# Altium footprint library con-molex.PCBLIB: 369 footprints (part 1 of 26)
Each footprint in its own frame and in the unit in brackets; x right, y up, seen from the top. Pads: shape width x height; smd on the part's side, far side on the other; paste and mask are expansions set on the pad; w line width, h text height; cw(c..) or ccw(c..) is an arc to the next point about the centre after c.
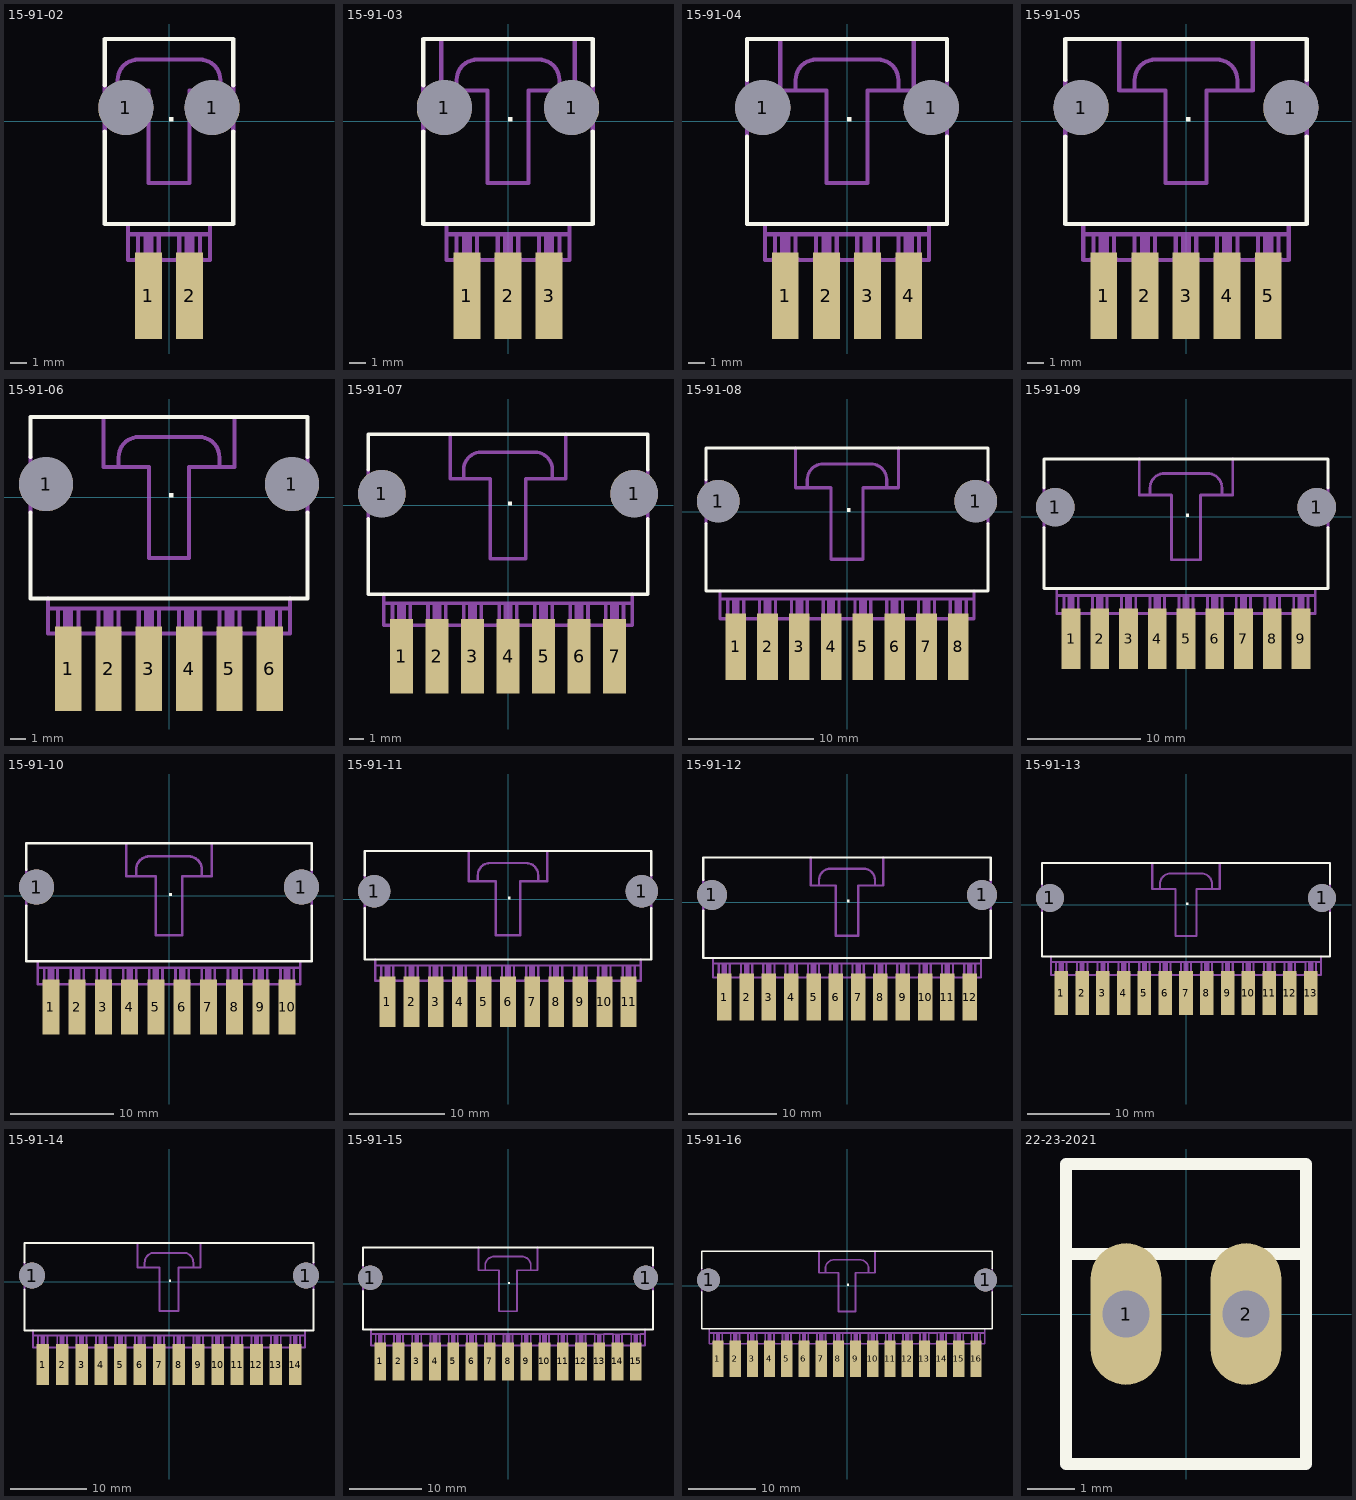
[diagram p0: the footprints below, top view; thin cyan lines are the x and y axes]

## 15-91-02 [mil]
pads (4):
  round 134 hole 134: 1(-105,33) 1(105,33)
  rect 65x210 smd: 1(-50,-425) 2(50,-425)
Top Overlay:
  region: 0,0 10,0 10,10 0,10
  lines w10: -156.25,-25 -156.25,-250 156.25,-250 156.25,-25 ; -156.25,87.5 -156.25,200 156.25,200 156.25,87.5
Mechanical 16:
  rectangle: 37.5,-425 62.5,-275
  rectangle: -62.5,-425 -37.5,-275
  lines w10: -156.25,-25 -156.25,75 ; -156.25,87.5 -156.25,75 ; -100,-275 -75,-275 ; -100,-250 -100,-337.5 -85,-337.5 ccw(c-85,-327.5) -75,-327.5 -75,-275 ; 100,-275 75,-275 ; 100,-250 100,-337.5 85,-337.5 cw(c85,-327.5) 75,-327.5 75,-275 ; 156.25,-25 156.25,75 ; 156.25,87.5 156.25,75 ; -156.25,75 -125,75 ; -125,75 -125,100 cw(c-75,100) -75,150 75,150 cw(c75,100) 125,100 125,75 ; -125,75 -50,75 -50,-150 50,-150 50,75 125,75 ; -75,-275 -25,-275 ; -25,-275 -25,-327.5 ccw(c-15,-327.5) -15,-337.5 15,-337.5 ccw(c15,-327.5) 25,-327.5 25,-275 ; -25,-275 25,-275 ; 25,-275 75,-275 ; 125,75 156.25,75

## 15-91-03 [mil]
pads (5):
  round 134 hole 134: 1(-155,33) 1(155,33)
  rect 65x210 smd: 1(-100,-425) 2(0,-425) 3(100,-425)
Top Overlay:
  region: 0,0 10,0 10,10 0,10
  lines w10: -206.25,-25 -206.25,-250 206.25,-250 206.25,-25 ; -206.25,87.5 -206.25,200 206.25,200 206.25,87.5
Mechanical 16:
  rectangle: 87.5,-425 112.5,-275
  rectangle: -12.5,-425 12.5,-275
  rectangle: -112.5,-425 -87.5,-275
  lines w10: -206.25,-25 -206.25,87.5 ; -162.5,200 -162.5,75 -125,75 ; -150,-275 -125,-275 ; -150,-250 -150,-337.5 -135,-337.5 ccw(c-135,-327.5) -125,-327.5 -125,-275 ; 150,-275 125,-275 ; 150,-250 150,-337.5 135,-337.5 cw(c135,-327.5) 125,-327.5 125,-275 ; 162.5,200 162.5,75 125,75 ; 206.25,-25 206.25,87.5 ; -125,-275 -75,-275 ; -125,75 -125,100 cw(c-75,100) -75,150 75,150 cw(c75,100) 125,100 125,75 ; -125,75 -50,75 -50,-150 50,-150 50,75 125,75 ; -75,-275 -75,-327.5 ccw(c-65,-327.5) -65,-337.5 -35,-337.5 ccw(c-35,-327.5) -25,-327.5 -25,-275 ; -75,-275 -25,-275 ; -25,-275 25,-275 ; 25,-275 25,-327.5 ccw(c35,-327.5) 35,-337.5 65,-337.5 ccw(c65,-327.5) 75,-327.5 75,-275 ; 25,-275 75,-275 ; 75,-275 125,-275

## 15-91-04 [mil]
pads (6):
  round 134 hole 134: 1(-205,33) 1(205,33)
  rect 65x210 smd: 1(-150,-425) 2(-50,-425) 3(50,-425) 4(150,-425)
Top Overlay:
  region: 0,0 10,0 10,10 0,10
  lines w10: -243.75,-37.5 -243.75,-250 243.75,-250 243.75,-37.5 ; -243.75,100 -243.75,200 243.75,200 243.75,100
Mechanical 16:
  rectangle: 137.5,-425 162.5,-275
  rectangle: 37.5,-425 62.5,-275
  rectangle: -62.5,-425 -37.5,-275
  rectangle: -162.5,-425 -137.5,-275
  lines w10: -243.75,-37.5 -243.75,100 ; -200,-275 -175,-275 ; -200,-250 -200,-337.5 -185,-337.5 ccw(c-185,-327.5) -175,-327.5 -175,-275 ; -162.5,200 -162.5,75 -125,75 ; 162.5,200 162.5,75 125,75 ; 200,-275 175,-275 ; 200,-250 200,-337.5 185,-337.5 cw(c185,-327.5) 175,-327.5 175,-275 ; 243.75,-37.5 243.75,100 ; -175,-275 -125,-275 ; -125,-275 -125,-327.5 ccw(c-115,-327.5) -115,-337.5 -85,-337.5 ccw(c-85,-327.5) -75,-327.5 -75,-275 ; -125,-275 -75,-275 ; -125,75 -125,100 cw(c-75,100) -75,150 75,150 cw(c75,100) 125,100 125,75 ; -125,75 -50,75 -50,-150 50,-150 50,75 125,75 ; -75,-275 -25,-275 ; -25,-275 25,-275 ; -25,-275 -25,-327.5 ccw(c-15,-327.5) -15,-337.5 15,-337.5 ccw(c15,-327.5) 25,-327.5 25,-275 ; 25,-275 75,-275 ; 75,-275 75,-327.5 ccw(c85,-327.5) 85,-337.5 115,-337.5 ccw(c115,-327.5) 125,-327.5 125,-275 ; 75,-275 125,-275 ; 125,-275 175,-275

## 15-91-05 [mil]
pads (7):
  round 134 hole 134: 1(-255,33) 1(255,33)
  rect 65x210 smd: 1(-200,-425) 2(-100,-425) 3(0,-425) 4(100,-425) 5(200,-425)
Top Overlay:
  region: 0,0 10,0 10,10 0,10
  lines w10: -293.75,-37.5 -293.75,-250 293.75,-250 293.75,-37.5 ; -293.75,100 -293.75,200 293.75,200 293.75,100
Mechanical 16:
  rectangle: 187.5,-425 212.5,-275
  rectangle: 87.5,-425 112.5,-275
  rectangle: -12.5,-425 12.5,-275
  rectangle: -112.5,-425 -87.5,-275
  rectangle: -212.5,-425 -187.5,-275
  lines w10: -293.75,-37.5 -293.75,100 ; -250,-275 -225,-275 ; -250,-250 -250,-337.5 -235,-337.5 ccw(c-235,-327.5) -225,-327.5 -225,-275 ; -162.5,200 -162.5,75 -125,75 ; 162.5,200 162.5,75 125,75 ; 250,-275 225,-275 ; 250,-250 250,-337.5 235,-337.5 cw(c235,-327.5) 225,-327.5 225,-275 ; 293.75,-37.5 293.75,100 ; -225,-275 -175,-275 ; -175,-275 -175,-327.5 ccw(c-165,-327.5) -165,-337.5 -135,-337.5 ccw(c-135,-327.5) -125,-327.5 -125,-275 ; -175,-275 -125,-275 ; -125,-275 -75,-275 ; -125,75 -125,100 cw(c-75,100) -75,150 75,150 cw(c75,100) 125,100 125,75 ; -125,75 -50,75 -50,-150 50,-150 50,75 125,75 ; -75,-275 -25,-275 ; -75,-275 -75,-327.5 ccw(c-65,-327.5) -65,-337.5 -35,-337.5 ccw(c-35,-327.5) -25,-327.5 -25,-275 ; -25,-275 25,-275 ; 25,-275 25,-327.5 ccw(c35,-327.5) 35,-337.5 65,-337.5 ccw(c65,-327.5) 75,-327.5 75,-275 ; 25,-275 75,-275 ; 75,-275 125,-275 ; 125,-275 125,-327.5 ccw(c135,-327.5) 135,-337.5 165,-337.5 ccw(c165,-327.5) 175,-327.5 175,-275 ; 125,-275 175,-275 ; 175,-275 225,-275

## 15-91-06 [mil]
pads (8):
  round 134 hole 134: 1(-305,33) 1(305,33)
  rect 65x210 smd: 1(-250,-425) 2(-150,-425) 3(-50,-425) 4(50,-425) 5(150,-425) 6(250,-425)
Top Overlay:
  region: 0,0 10,0 10,10 0,10
  lines w10: -343.75,-37.5 -343.75,-250 343.75,-250 343.75,-37.5 ; -343.75,100 -343.75,200 343.75,200 343.75,100
Mechanical 16:
  rectangle: 237.5,-425 262.5,-275
  rectangle: 137.5,-425 162.5,-275
  rectangle: 37.5,-425 62.5,-275
  rectangle: -62.5,-425 -37.5,-275
  rectangle: -162.5,-425 -137.5,-275
  rectangle: -262.5,-425 -237.5,-275
  lines w10: -343.75,-37.5 -343.75,100 ; -300,-275 -275,-275 ; -300,-250 -300,-337.5 -285,-337.5 ccw(c-285,-327.5) -275,-327.5 -275,-275 ; -162.5,200 -162.5,75 -125,75 ; 162.5,200 162.5,75 125,75 ; 300,-275 275,-275 ; 300,-250 300,-337.5 285,-337.5 cw(c285,-327.5) 275,-327.5 275,-275 ; 343.75,-37.5 343.75,100 ; -275,-275 -225,-275 ; -225,-275 -225,-327.5 ccw(c-215,-327.5) -215,-337.5 -185,-337.5 ccw(c-185,-327.5) -175,-327.5 -175,-275 ; -225,-275 -175,-275 ; -175,-275 -125,-275 ; -125,-275 -75,-275 ; -125,-275 -125,-327.5 ccw(c-115,-327.5) -115,-337.5 -85,-337.5 ccw(c-85,-327.5) -75,-327.5 -75,-275 ; -125,75 -125,100 cw(c-75,100) -75,150 75,150 cw(c75,100) 125,100 125,75 ; -125,75 -50,75 -50,-150 50,-150 50,75 125,75 ; -75,-275 -25,-275 ; -25,-275 -25,-327.5 ccw(c-15,-327.5) -15,-337.5 15,-337.5 ccw(c15,-327.5) 25,-327.5 25,-275 ; -25,-275 25,-275 ; 25,-275 75,-275 ; 75,-275 125,-275 ; 75,-275 75,-327.5 ccw(c85,-327.5) 85,-337.5 115,-337.5 ccw(c115,-327.5) 125,-327.5 125,-275 ; 125,-275 175,-275 ; 175,-275 175,-327.5 ccw(c185,-327.5) 185,-337.5 215,-337.5 ccw(c215,-327.5) 225,-327.5 225,-275 ; 175,-275 225,-275 ; 225,-275 275,-275

## 15-91-07 [mil]
pads (9):
  round 134 hole 134: 1(-355,33) 1(355,33)
  rect 65x210 smd: 1(-300,-425) 2(-200,-425) 3(-100,-425) 4(0,-425) 5(100,-425) 6(200,-425) 7(300,-425)
Top Overlay:
  region: 0,0 10,0 10,10 0,10
  lines w10: -393.75,-37.5 -393.75,-250 393.75,-250 393.75,-37.5 ; -393.75,100 -393.75,200 393.75,200 393.75,100
Mechanical 16:
  rectangle: -312.5,-425 -287.5,-275
  rectangle: -212.5,-425 -187.5,-275
  rectangle: -112.5,-425 -87.5,-275
  rectangle: 87.5,-425 112.5,-275
  rectangle: 187.5,-425 212.5,-275
  rectangle: 287.5,-425 312.5,-275
  rectangle: -12.5,-425 12.5,-275
  lines w10: -393.75,-37.5 -393.75,100 ; -350,-275 -325,-275 ; -350,-250 -350,-337.5 -335,-337.5 ccw(c-335,-327.5) -325,-327.5 -325,-275 ; -162.5,200 -162.5,75 -125,75 ; 162.5,200 162.5,75 125,75 ; 350,-250 350,-275 ; 393.75,-37.5 393.75,100 ; -325,-275 -275,-275 ; -275,-275 -225,-275 ; -275,-275 -275,-327.5 ccw(c-265,-327.5) -265,-337.5 -235,-337.5 ccw(c-235,-327.5) -225,-327.5 -225,-275 ; -225,-275 -175,-275 ; -175,-275 -125,-275 ; -175,-275 -175,-327.5 ccw(c-165,-327.5) -165,-337.5 -135,-337.5 ccw(c-135,-327.5) -125,-327.5 -125,-275 ; -125,-275 -75,-275 ; -125,75 -50,75 -50,-150 50,-150 50,75 125,75 ; -125,75 -125,100 cw(c-75,100) -75,150 75,150 cw(c75,100) 125,100 125,75 ; -75,-275 -75,-327.5 ccw(c-65,-327.5) -65,-337.5 -35,-337.5 ccw(c-35,-327.5) -25,-327.5 -25,-275 ; -75,-275 -25,-275 ; -25,-275 25,-275 ; 25,-275 75,-275 ; 25,-275 25,-327.5 ccw(c34.99,-327.51) 35,-337.5 65,-337.5 ccw(c65,-327.5) 75,-327.5 75,-275 ; 75,-275 125,-275 ; 125,-275 175,-275 ; 125,-275 125,-327.5 ccw(c135,-327.5) 135,-337.5 165,-337.5 ccw(c165,-327.5) 175,-327.5 175,-275 ; 175,-275 225,-275 ; 225,-275 275,-275 ; 225,-275 225,-327.5 ccw(c235,-327.5) 235,-337.5 265,-337.5 ccw(c265,-327.5) 275,-327.5 275,-275 ; 275,-275 325,-275 ; 325,-275 350,-275 ; 325,-275 325,-327.5 ccw(c335,-327.5) 335,-337.5 350,-337.5 350,-275

## 15-91-08 [mil]
pads (10):
  round 134 hole 134: 1(-405,33) 1(405,33)
  rect 65x210 smd: 1(-350,-425) 2(-250,-425) 3(-150,-425) 4(-50,-425) 5(50,-425) 6(150,-425) 7(250,-425) 8(350,-425)
Top Overlay:
  region: 0,0 10,0 10,10 0,10
  lines w10: -443.75,-37.5 -443.75,-250 443.75,-250 443.75,-37.5 ; -443.75,100 -443.75,200 443.75,200 443.75,100
Mechanical 16:
  rectangle: -362.5,-425 -337.5,-275
  rectangle: -262.5,-425 -237.5,-275
  rectangle: -162.5,-425 -137.5,-275
  rectangle: -62.5,-425 -37.5,-275
  rectangle: 37.5,-425 62.5,-275
  rectangle: 137.5,-425 162.5,-275
  rectangle: 237.5,-425 262.5,-275
  rectangle: 337.5,-425 362.5,-275
  lines w10: -443.75,-37.5 -443.75,100 ; -400,-275 -375,-275 ; -400,-250 -400,-337.5 -385,-337.5 ccw(c-385,-327.5) -375,-327.5 -375,-275 ; -162.5,200 -162.5,75 -125,75 ; 162.5,200 162.5,75 125,75 ; 400,-275 375,-275 ; 400,-250 400,-337.5 385,-337.5 cw(c385,-327.5) 375,-327.5 375,-275 ; 443.75,-37.5 443.75,100 ; -375,-275 -325,-275 ; -325,-275 -275,-275 ; -325,-275 -325,-327.5 ccw(c-315,-327.5) -315,-337.5 -285,-337.5 ccw(c-285,-327.5) -275,-327.5 -275,-275 ; -275,-275 -225,-275 ; -225,-275 -225,-327.5 ccw(c-215,-327.5) -215,-337.5 -185,-337.5 ccw(c-185,-327.5) -175,-327.5 -175,-275 ; -225,-275 -175,-275 ; -175,-275 -125,-275 ; -125,-275 -75,-275 ; -125,-275 -125,-327.5 ccw(c-115,-327.5) -115,-337.5 -85,-337.5 ccw(c-85,-327.5) -75,-327.5 -75,-275 ; -125,75 -50,75 -50,-150 50,-150 50,75 125,75 ; -125,75 -125,100 cw(c-75,100) -75,150 75,150 cw(c75,100) 125,100 125,75 ; -75,-275 -25,-275 ; -25,-275 -25,-327.5 ccw(c-15,-327.5) -15,-337.5 15,-337.5 ccw(c15,-327.5) 25,-327.5 25,-275 ; -25,-275 25,-275 ; 25,-275 75,-275 ; 75,-275 125,-275 ; 75,-275 75,-327.5 ccw(c85,-327.5) 85,-337.5 115,-337.5 ccw(c115,-327.5) 125,-327.5 125,-275 ; 125,-275 175,-275 ; 175,-275 175,-327.5 ccw(c185,-327.5) 185,-337.5 215,-337.5 ccw(c215,-327.5) 225,-327.5 225,-275 ; 175,-275 225,-275 ; 225,-275 275,-275 ; 275,-275 325,-275 ; 275,-275 275,-327.5 ccw(c285,-327.5) 285,-337.5 315,-337.5 ccw(c315,-327.5) 325,-327.5 325,-275 ; 325,-275 375,-275

## 15-91-09 [mil]
pads (11):
  round 134 hole 134: 1(-455,33) 1(455,33)
  rect 65x210 smd: 1(-400,-425) 2(-300,-425) 3(-200,-425) 4(-100,-425) 5(0,-425) 6(100,-425) 7(200,-425) 8(300,-425) 9(400,-425)
Top Overlay:
  region: 0,0 10,0 10,10 0,10
  lines w10: -493.75,-37.5 -493.75,-250 493.75,-250 493.75,-37.5 ; -493.75,100 -493.75,200 493.75,200 493.75,100
Mechanical 16:
  rectangle: -412.5,-425 -387.5,-275
  rectangle: -312.5,-425 -287.5,-275
  rectangle: -212.5,-425 -187.5,-275
  rectangle: -112.5,-425 -87.5,-275
  rectangle: -12.5,-425 12.5,-275
  rectangle: 87.5,-425 112.5,-275
  rectangle: 187.5,-425 212.5,-275
  rectangle: 287.5,-425 312.5,-275
  rectangle: 387.5,-425 412.5,-275
  lines w10: -493.75,-37.5 -493.75,100 ; -450,-275 -425,-275 ; -450,-250 -450,-337.5 -435,-337.5 ccw(c-435,-327.5) -425,-327.5 -425,-275 ; -162.5,200 -162.5,75 -125,75 ; 162.5,200 162.5,75 125,75 ; 450,-275 425,-275 ; 450,-250 450,-337.5 435,-337.5 cw(c435,-327.5) 425,-327.5 425,-275 ; 493.75,-37.5 493.75,100 ; -425,-275 -375,-275 ; -375,-275 -325,-275 ; -375,-275 -375,-327.5 ccw(c-365,-327.5) -365,-337.5 -335,-337.5 ccw(c-335,-327.5) -325,-327.5 -325,-275 ; -325,-275 -275,-275 ; -275,-275 -225,-275 ; -275,-275 -275,-327.5 ccw(c-265,-327.5) -265,-337.5 -235,-337.5 ccw(c-235,-327.5) -225,-327.5 -225,-275 ; -225,-275 -175,-275 ; -175,-275 -175,-327.5 ccw(c-165,-327.5) -165,-337.5 -135,-337.5 ccw(c-135,-327.5) -125,-327.5 -125,-275 ; -175,-275 -125,-275 ; -125,-275 -75,-275 ; -125,75 -50,75 -50,-150 50,-150 50,75 125,75 ; -125,75 -125,100 cw(c-75,100) -75,150 75,150 cw(c75,100) 125,100 125,75 ; -75,-275 -25,-275 ; -75,-275 -75,-327.5 ccw(c-65,-327.5) -65,-337.5 -35,-337.5 ccw(c-35,-327.5) -25,-327.5 -25,-275 ; -25,-275 25,-275 ; 25,-275 75,-275 ; 25,-275 25,-327.5 ccw(c35,-327.5) 35,-337.5 65,-337.5 ccw(c65,-327.5) 75,-327.5 75,-275 ; 75,-275 125,-275 ; 125,-275 125,-327.5 ccw(c135,-327.5) 135,-337.5 165,-337.5 ccw(c165,-327.5) 175,-327.5 175,-275 ; 125,-275 175,-275 ; 175,-275 225,-275 ; 225,-275 275,-275 ; 225,-275 225,-327.5 ccw(c235,-327.5) 235,-337.5 265,-337.5 ccw(c265,-327.5) 275,-327.5 275,-275 ; 275,-275 325,-275 ; 325,-275 375,-275 ; 325,-275 325,-327.5 ccw(c335,-327.5) 335,-337.5 365,-337.5 ccw(c365,-327.5) 375,-327.5 375,-275 ; 375,-275 425,-275

## 15-91-10 [mil]
pads (12):
  round 134 hole 134: 1(-505,33) 1(505,33)
  rect 65x210 smd: 1(-450,-425) 2(-350,-425) 3(-250,-425) 4(-150,-425) 5(-50,-425) 6(50,-425) 7(150,-425) 8(250,-425) 9(350,-425) 10(450,-425)
Top Overlay:
  region: 0,0 10,0 10,10 0,10
  lines w10: -543.75,-37.5 -543.75,-250 543.75,-250 543.75,-37.5 ; -543.75,100 -543.75,200 543.75,200 543.75,100
Mechanical 16:
  rectangle: -462.5,-425 -437.5,-275
  rectangle: -362.5,-425 -337.5,-275
  rectangle: -262.5,-425 -237.5,-275
  rectangle: -162.5,-425 -137.5,-275
  rectangle: -62.5,-425 -37.5,-275
  rectangle: 37.5,-425 62.5,-275
  rectangle: 137.5,-425 162.5,-275
  rectangle: 237.5,-425 262.5,-275
  rectangle: 337.5,-425 362.5,-275
  rectangle: 437.5,-425 462.5,-275
  lines w10: -543.75,-37.5 -543.75,100 ; -500,-275 -475,-275 ; -500,-250 -500,-337.5 -485,-337.5 ccw(c-485,-327.5) -475,-327.5 -475,-275 ; -162.5,200 -162.5,75 -125,75 ; 162.5,200 162.5,75 125,75 ; 500,-275 475,-275 ; 500,-250 500,-337.5 485,-337.5 cw(c485,-327.5) 475,-327.5 475,-275 ; 543.75,-37.5 543.75,100 ; -475,-275 -425,-275 ; -425,-275 -375,-275 ; -425,-275 -425,-327.5 ccw(c-415,-327.5) -415,-337.5 -385,-337.5 ccw(c-385,-327.5) -375,-327.5 -375,-275 ; -375,-275 -325,-275 ; -325,-275 -325,-327.5 ccw(c-315,-327.5) -315,-337.5 -285,-337.5 ccw(c-285,-327.5) -275,-327.5 -275,-275 ; -325,-275 -275,-275 ; -275,-275 -225,-275 ; -225,-275 -175,-275 ; -225,-275 -225,-327.5 ccw(c-215,-327.5) -215,-337.5 -185,-337.5 ccw(c-185,-327.5) -175,-327.5 -175,-275 ; -175,-275 -125,-275 ; -125,-275 -125,-327.5 ccw(c-115,-327.5) -115,-337.5 -85,-337.5 ccw(c-85,-327.5) -75,-327.5 -75,-275 ; -125,-275 -75,-275 ; -125,75 -50,75 -50,-150 50,-150 50,75 125,75 ; -125,75 -125,100 cw(c-75,100) -75,150 75,150 cw(c75,100) 125,100 125,75 ; -75,-275 -25,-275 ; -25,-275 25,-275 ; -25,-275 -25,-327.5 ccw(c-15,-327.5) -15,-337.5 15,-337.5 ccw(c15,-327.5) 25,-327.5 25,-275 ; 25,-275 75,-275 ; 75,-275 75,-327.5 ccw(c85,-327.5) 85,-337.5 115,-337.5 ccw(c115,-327.5) 125,-327.5 125,-275 ; 75,-275 125,-275 ; 125,-275 175,-275 ; 175,-275 225,-275 ; 175,-275 175,-327.5 ccw(c185,-327.5) 185,-337.5 215,-337.5 ccw(c215,-327.5) 225,-327.5 225,-275 ; 225,-275 275,-275 ; 275,-275 275,-327.5 ccw(c285,-327.5) 285,-337.5 315,-337.5 ccw(c315,-327.5) 325,-327.5 325,-275 ; 275,-275 325,-275 ; 325,-275 375,-275 ; 375,-275 425,-275 ; 375,-275 375,-327.5 ccw(c385,-327.5) 385,-337.5 415,-337.5 ccw(c415,-327.5) 425,-327.5 425,-275 ; 425,-275 475,-275

## 15-91-11 [mil]
pads (13):
  round 134 hole 134: 1(-555,33) 1(555,33)
  rect 65x210 smd: 1(-500,-425) 2(-400,-425) 3(-300,-425) 4(-200,-425) 5(-100,-425) 6(0,-425) 7(100,-425) 8(200,-425) 9(300,-425) 10(400,-425) 11(500,-425)
Top Overlay:
  region: 0,0 10,0 10,10 0,10
  lines w10: -593.75,-37.5 -593.75,-250 593.75,-250 593.75,-37.5 ; -593.75,100 -593.75,200 593.75,200 593.75,100
Mechanical 16:
  rectangle: -512.5,-425 -487.5,-275
  rectangle: -412.5,-425 -387.5,-275
  rectangle: -312.5,-425 -287.5,-275
  rectangle: 287.5,-425 312.5,-275
  rectangle: 387.5,-425 412.5,-275
  rectangle: 487.5,-425 512.5,-275
  rectangle: -212.5,-425 -187.5,-275
  rectangle: -112.5,-425 -87.5,-275
  rectangle: -12.5,-425 12.5,-275
  rectangle: 87.5,-425 112.5,-275
  rectangle: 187.5,-425 212.5,-275
  lines w10: -593.75,-37.5 -593.75,100 ; -550,-275 -525,-275 ; -550,-250 -550,-337.5 -535,-337.5 ccw(c-535,-327.5) -525,-327.5 -525,-275 ; -162.5,200 -162.5,75 -125,75 ; 162.5,200 162.5,75 125,75 ; 550,-275 525,-275 ; 550,-250 550,-337.5 535,-337.5 cw(c535,-327.5) 525,-327.5 525,-275 ; 593.75,-37.5 593.75,100 ; -525,-275 -475,-275 ; -475,-275 -425,-275 ; -475,-275 -475,-327.5 ccw(c-465,-327.5) -465,-337.5 -435,-337.5 ccw(c-435,-327.5) -425,-327.5 -425,-275 ; -425,-275 -375,-275 ; -375,-275 -325,-275 ; -375,-275 -375,-327.5 ccw(c-365,-327.5) -365,-337.5 -335,-337.5 ccw(c-335,-327.5) -325,-327.5 -325,-275 ; -325,-275 -275,-275 ; -275,-275 -275,-327.5 ccw(c-265,-327.5) -265,-337.5 -235,-337.5 ccw(c-235,-327.5) -225,-327.5 -225,-275 ; -275,-275 -225,-275 ; -225,-275 -175,-275 ; -175,-275 -125,-275 ; -175,-275 -175,-327.5 ccw(c-165,-327.5) -165,-337.5 -135,-337.5 ccw(c-135,-327.5) -125,-327.5 -125,-275 ; -125,-275 -75,-275 ; -125,75 -50,75 -50,-150 50,-150 50,75 125,75 ; -125,75 -125,100 cw(c-75,100) -75,150 75,150 cw(c75,100) 125,100 125,75 ; -75,-275 -25,-275 ; -75,-275 -75,-327.5 ccw(c-65,-327.5) -65,-337.5 -35,-337.5 ccw(c-35,-327.5) -25,-327.5 -25,-275 ; -25,-275 25,-275 ; 25,-275 25,-327.5 ccw(c35,-327.5) 35,-337.5 65,-337.5 ccw(c65,-327.5) 75,-327.5 75,-275 ; 25,-275 75,-275 ; 75,-275 125,-275 ; 125,-275 125,-327.5 ccw(c135,-327.5) 135,-337.5 165,-337.5 ccw(c165,-327.5) 175,-327.5 175,-275 ; 125,-275 175,-275 ; 175,-275 225,-275 ; 225,-275 275,-275 ; 225,-275 225,-327.5 ccw(c235,-327.5) 235,-337.5 265,-337.5 ccw(c265,-327.5) 275,-327.5 275,-275 ; 275,-275 325,-275 ; 325,-275 375,-275 ; 325,-275 325,-327.5 ccw(c335,-327.5) 335,-337.5 365,-337.5 ccw(c365,-327.5) 375,-327.5 375,-275 ; 375,-275 425,-275 ; 425,-275 475,-275 ; 425,-275 425,-327.5 ccw(c435,-327.5) 435,-337.5 465,-337.5 ccw(c465,-327.5) 475,-327.5 475,-275 ; 475,-275 525,-275

## 15-91-12 [mil]
pads (14):
  round 134 hole 134: 1(-605,33) 1(605,33)
  rect 65x210 smd: 1(-550,-425) 2(-450,-425) 3(-350,-425) 4(-250,-425) 5(-150,-425) 6(-50,-425) 7(50,-425) 8(150,-425) 9(250,-425) 10(350,-425) 11(450,-425) 12(550,-425)
Top Overlay:
  region: 0,0 10,0 10,10 0,10
  lines w10: -643.75,-37.5 -643.75,-250 643.75,-250 643.75,-37.5 ; -643.75,100 -643.75,200 643.75,200 643.75,100
Mechanical 16:
  rectangle: -562.5,-425 -537.5,-275
  rectangle: -462.5,-425 -437.5,-275
  rectangle: -362.5,-425 -337.5,-275
  rectangle: -262.5,-425 -237.5,-275
  rectangle: -162.5,-425 -137.5,-275
  rectangle: -62.5,-425 -37.5,-275
  rectangle: 37.5,-425 62.5,-275
  rectangle: 137.5,-425 162.5,-275
  rectangle: 237.5,-425 262.5,-275
  rectangle: 337.5,-425 362.5,-275
  rectangle: 437.5,-425 462.5,-275
  rectangle: 537.5,-425 562.5,-275
  lines w10: -643.75,-37.5 -643.75,100 ; -600,-275 -575,-275 ; -600,-250 -600,-337.5 -585,-337.5 ccw(c-585,-327.5) -575,-327.5 -575,-275 ; -162.5,200 -162.5,75 -125,75 ; 162.5,200 162.5,75 125,75 ; 600,-275 575,-275 ; 600,-250 600,-337.5 585,-337.5 cw(c585,-327.5) 575,-327.5 575,-275 ; 643.75,-37.5 643.75,100 ; -575,-275 -525,-275 ; -525,-275 -475,-275 ; -525,-275 -525,-327.5 ccw(c-515,-327.5) -515,-337.5 -485,-337.5 ccw(c-485,-327.5) -475,-327.5 -475,-275 ; -475,-275 -425,-275 ; -425,-275 -425,-327.5 ccw(c-415,-327.5) -415,-337.5 -385,-337.5 ccw(c-385,-327.5) -375,-327.5 -375,-275 ; -425,-275 -375,-275 ; -375,-275 -325,-275 ; -325,-275 -275,-275 ; -325,-275 -325,-327.5 ccw(c-315,-327.5) -315,-337.5 -285,-337.5 ccw(c-285,-327.5) -275,-327.5 -275,-275 ; -275,-275 -225,-275 ; -225,-275 -225,-327.5 ccw(c-215,-327.5) -215,-337.5 -185,-337.5 ccw(c-185,-327.5) -175,-327.5 -175,-275 ; -225,-275 -175,-275 ; -175,-275 -125,-275 ; -125,-275 -75,-275 ; -125,-275 -125,-327.5 ccw(c-115,-327.5) -115,-337.5 -85,-337.5 ccw(c-85,-327.5) -75,-327.5 -75,-275 ; -125,75 -50,75 -50,-150 50,-150 50,75 125,75 ; -125,75 -125,100 cw(c-75,100) -75,150 75,150 cw(c75,100) 125,100 125,75 ; -75,-275 -25,-275 ; -25,-275 -25,-327.5 ccw(c-15,-327.5) -15,-337.5 15,-337.5 ccw(c15,-327.5) 25,-327.5 25,-275 ; -25,-275 25,-275 ; 25,-275 75,-275 ; 75,-275 125,-275 ; 75,-275 75,-327.5 ccw(c85,-327.5) 85,-337.5 115,-337.5 ccw(c115,-327.5) 125,-327.5 125,-275 ; 125,-275 175,-275 ; 175,-275 175,-327.5 ccw(c185,-327.5) 185,-337.5 215,-337.5 ccw(c215,-327.5) 225,-327.5 225,-275 ; 175,-275 225,-275 ; 225,-275 275,-275 ; 275,-275 325,-275 ; 275,-275 275,-327.5 ccw(c285,-327.5) 285,-337.5 315,-337.5 ccw(c315,-327.5) 325,-327.5 325,-275 ; 325,-275 375,-275 ; 375,-275 375,-327.5 ccw(c385,-327.5) 385,-337.5 415,-337.5 ccw(c415,-327.5) 425,-327.5 425,-275 ; 375,-275 425,-275 ; 425,-275 475,-275 ; 475,-275 525,-275 ; 475,-275 475,-327.5 ccw(c485,-327.5) 485,-337.5 515,-337.5 ccw(c515,-327.5) 525,-327.5 525,-275 ; 525,-275 575,-275

## 15-91-13 [mil]
pads (15):
  round 134 hole 134: 1(-655,33) 1(655,33)
  rect 65x210 smd: 1(-600,-425) 2(-500,-425) 3(-400,-425) 4(-300,-425) 5(-200,-425) 6(-100,-425) 7(0,-425) 8(100,-425) 9(200,-425) 10(300,-425) 11(400,-425) 12(500,-425) 13(600,-425)
Top Overlay:
  region: 0,0 10,0 10,10 0,10
  lines w10: -693.75,-37.5 -693.75,-250 693.75,-250 693.75,-37.5 ; -693.75,100 -693.75,200 693.75,200 693.75,100
Mechanical 16:
  rectangle: -612.5,-425 -587.5,-275
  rectangle: -512.5,-425 -487.5,-275
  rectangle: -412.5,-425 -387.5,-275
  rectangle: -312.5,-425 -287.5,-275
  rectangle: -212.5,-425 -187.5,-275
  rectangle: -112.5,-425 -87.5,-275
  rectangle: -12.5,-425 12.5,-275
  rectangle: 87.5,-425 112.5,-275
  rectangle: 187.5,-425 212.5,-275
  rectangle: 287.5,-425 312.5,-275
  rectangle: 387.5,-425 412.5,-275
  rectangle: 487.5,-425 512.5,-275
  rectangle: 587.5,-425 612.5,-275
  lines w8: 575,-275 625,-275
  lines w10: -693.75,-37.5 -693.75,100 ; -650,-275 -625,-275 ; -650,-250 -650,-337.5 -635,-337.5 ccw(c-635,-327.5) -625,-327.5 -625,-275 ; -162.5,200 -162.5,75 -125,75 ; 162.5,200 162.5,75 125,75 ; 650,-275 625,-275 625,-327.5 ccw(c635,-327.5) 635,-337.5 650,-337.5 650,-250 ; 693.75,-37.5 693.75,100 ; -625,-275 -575,-275 ; -575,-275 -525,-275 ; -575,-275 -575,-327.5 ccw(c-565,-327.5) -565,-337.5 -535,-337.5 ccw(c-535,-327.5) -525,-327.5 -525,-275 ; -525,-275 -475,-275 ; -475,-275 -475,-327.5 ccw(c-465,-327.5) -465,-337.5 -435,-337.5 ccw(c-435,-327.5) -425,-327.5 -425,-275 ; -475,-275 -425,-275 ; -425,-275 -375,-275 ; -375,-275 -325,-275 ; -375,-275 -375,-327.5 ccw(c-365,-327.5) -365,-337.5 -335,-337.5 ccw(c-335,-327.5) -325,-327.5 -325,-275 ; -325,-275 -275,-275 ; -275,-275 -275,-327.5 ccw(c-265,-327.5) -265,-337.5 -235,-337.5 ccw(c-235,-327.5) -225,-327.5 -225,-275 ; -275,-275 -225,-275 ; -225,-275 -175,-275 ; -175,-275 -125,-275 ; -175,-275 -175,-327.5 ccw(c-165,-327.5) -165,-337.5 -135,-337.5 ccw(c-135,-327.5) -125,-327.5 -125,-275 ; -125,-275 -75,-275 ; -125,75 -50,75 -50,-150 50,-150 50,75 125,75 ; -125,75 -125,100 cw(c-75,100) -75,150 75,150 cw(c75,100) 125,100 125,75 ; -75,-275 -75,-327.5 ccw(c-65,-327.5) -65,-337.5 -35,-337.5 ccw(c-35,-327.5) -25,-327.5 -25,-275 ; -75,-275 -25,-275 ; -25,-275 25,-275 ; 25,-275 75,-275 ; 25,-275 25,-327.5 ccw(c35,-327.5) 35,-337.5 65,-337.5 ccw(c65,-327.5) 75,-327.5 75,-275 ; 75,-275 125,-275 ; 125,-275 125,-327.5 ccw(c135,-327.5) 135,-337.5 165,-337.5 ccw(c165,-327.5) 175,-327.5 175,-275 ; 125,-275 175,-275 ; 175,-275 225,-275 ; 225,-275 275,-275 ; 225,-275 225,-327.5 ccw(c235,-327.5) 235,-337.5 265,-337.5 ccw(c265,-327.5) 275,-327.5 275,-275 ; 275,-275 325,-275 ; 325,-275 325,-327.5 ccw(c335,-327.5) 335,-337.5 365,-337.5 ccw(c365,-327.5) 375,-327.5 375,-275 ; 325,-275 375,-275 ; 375,-275 425,-275 ; 425,-275 475,-275 ; 425,-275 425,-327.5 ccw(c435,-327.5) 435,-337.5 465,-337.5 ccw(c465,-327.5) 475,-327.5 475,-275 ; 475,-275 525,-275 ; 525,-275 575,-275 575,-327.5 cw(c565,-327.5) 565,-337.5 535,-337.5 cw(c535,-327.5) 525,-327.5 525,-275

## 15-91-14 [mil]
pads (16):
  round 134 hole 134: 1(-705,33) 1(705,33)
  rect 65x210 smd: 1(-650,-425) 2(-550,-425) 3(-450,-425) 4(-350,-425) 5(-250,-425) 6(-150,-425) 7(-50,-425) 8(50,-425) 9(150,-425) 10(250,-425) 11(350,-425) 12(450,-425) 13(550,-425) 14(650,-425)
Top Overlay:
  region: 0,0 10,0 10,10 0,10
  lines w10: -743.75,-37.5 -743.75,-250 743.75,-250 743.75,-37.5 ; -743.75,100 -743.75,200 743.75,200 743.75,100
Mechanical 16:
  rectangle: -662.5,-425 -637.5,-275
  rectangle: -562.5,-425 -537.5,-275
  rectangle: -462.5,-425 -437.5,-275
  rectangle: -362.5,-425 -337.5,-275
  rectangle: -262.5,-425 -237.5,-275
  rectangle: -162.5,-425 -137.5,-275
  rectangle: -62.5,-425 -37.5,-275
  rectangle: 37.5,-425 62.5,-275
  rectangle: 137.5,-425 162.5,-275
  rectangle: 237.5,-425 262.5,-275
  rectangle: 337.5,-425 362.5,-275
  rectangle: 437.5,-425 462.5,-275
  rectangle: 537.5,-425 562.5,-275
  rectangle: 637.5,-425 662.5,-275
  lines w8: 525,-275 575,-275 ; 625,-275 675,-275
  lines w10: -743.75,-37.5 -743.75,100 ; -700,-275 -675,-275 ; -700,-250 -700,-337.5 -685,-337.5 ccw(c-685,-327.5) -675,-327.5 -675,-275 ; -162.5,200 -162.5,75 -125,75 ; 162.5,200 162.5,75 125,75 ; 700,-275 675,-275 675,-327.5 ccw(c685,-327.5) 685,-337.5 700,-337.5 700,-250 ; 743.75,-37.5 743.75,100 ; -675,-275 -625,-275 ; -625,-275 -575,-275 ; -625,-275 -625,-327.5 ccw(c-615,-327.5) -615,-337.5 -585,-337.5 ccw(c-585,-327.5) -575,-327.5 -575,-275 ; -575,-275 -525,-275 ; -525,-275 -525,-327.5 ccw(c-515,-327.5) -515,-337.5 -485,-337.5 ccw(c-485,-327.5) -475,-327.5 -475,-275 ; -525,-275 -475,-275 ; -475,-275 -425,-275 ; -425,-275 -375,-275 ; -425,-275 -425,-327.5 ccw(c-415,-327.5) -415,-337.5 -385,-337.5 ccw(c-385,-327.5) -375,-327.5 -375,-275 ; -375,-275 -325,-275 ; -325,-275 -325,-327.5 ccw(c-315,-327.5) -315,-337.5 -285,-337.5 ccw(c-285,-327.5) -275,-327.5 -275,-275 ; -325,-275 -275,-275 ; -275,-275 -225,-275 ; -225,-275 -175,-275 ; -225,-275 -225,-327.5 ccw(c-215,-327.5) -215,-337.5 -185,-337.5 ccw(c-185,-327.5) -175,-327.5 -175,-275 ; -175,-275 -125,-275 ; -125,-275 -125,-327.5 ccw(c-115,-327.5) -115,-337.5 -85,-337.5 ccw(c-85,-327.5) -75,-327.5 -75,-275 ; -125,-275 -75,-275 ; -125,75 -50,75 -50,-150 50,-150 50,75 125,75 ; -125,75 -125,100 cw(c-75,100) -75,150 75,150 cw(c75,100) 125,100 125,75 ; -75,-275 -25,-275 ; -25,-275 25,-275 ; -25,-275 -25,-327.5 ccw(c-15,-327.5) -15,-337.5 15,-337.5 ccw(c15,-327.5) 25,-327.5 25,-275 ; 25,-275 75,-275 ; 75,-275 75,-327.5 ccw(c85,-327.5) 85,-337.5 115,-337.5 ccw(c115,-327.5) 125,-327.5 125,-275 ; 75,-275 125,-275 ; 125,-275 175,-275 ; 175,-275 225,-275 ; 175,-275 175,-327.5 ccw(c185,-327.5) 185,-337.5 215,-337.5 ccw(c215,-327.5) 225,-327.5 225,-275 ; 225,-275 275,-275 ; 275,-275 275,-327.5 ccw(c285,-327.5) 285,-337.5 315,-337.5 ccw(c315,-327.5) 325,-327.5 325,-275 ; 275,-275 325,-275 ; 325,-275 375,-275 ; 375,-275 425,-275 ; 375,-275 375,-327.5 ccw(c385,-327.5) 385,-337.5 415,-337.5 ccw(c415,-327.5) 425,-327.5 425,-275 ; 425,-275 475,-275 ; 475,-275 525,-275 525,-327.5 cw(c515,-327.5) 515,-337.5 485,-337.5 cw(c485,-327.5) 475,-327.5 475,-275 ; 575,-327.5 575,-275 625,-275 625,-327.5 cw(c615,-327.5) 615,-337.5 585,-337.5 cw(c585,-327.5) 575,-327.5

## 15-91-15 [mil]
pads (17):
  round 134 hole 134: 1(-755,33) 1(755,33)
  rect 65x210 smd: 1(-700,-425) 2(-600,-425) 3(-500,-425) 4(-400,-425) 5(-300,-425) 6(-200,-425) 7(-100,-425) 8(0,-425) 9(100,-425) 10(200,-425) 11(300,-425) 12(400,-425) 13(500,-425) 14(600,-425) 15(700,-425)
Top Overlay:
  region: 0,0 10,0 10,10 0,10
  lines w10: -793.75,-37.5 -793.75,-250 793.75,-250 793.75,-37.5 ; -793.75,100 -793.75,200 793.75,200 793.75,100
Mechanical 16:
  rectangle: -712.5,-425 -687.5,-275
  rectangle: -612.5,-425 -587.5,-275
  rectangle: -512.5,-425 -487.5,-275
  rectangle: -412.5,-425 -387.5,-275
  rectangle: -312.5,-425 -287.5,-275
  rectangle: -212.5,-425 -187.5,-275
  rectangle: -112.5,-425 -87.5,-275
  rectangle: -12.5,-425 12.5,-275
  rectangle: 87.5,-425 112.5,-275
  rectangle: 187.5,-425 212.5,-275
  rectangle: 287.5,-425 312.5,-275
  rectangle: 387.5,-425 412.5,-275
  rectangle: 487.5,-425 512.5,-275
  rectangle: 687.5,-425 712.5,-275
  rectangle: 587.5,-425 612.5,-275
  lines w8: 475,-275 525,-275 ; 575,-275 625,-275 ; 675,-275 725,-275
  lines w10: -793.75,-37.5 -793.75,100 ; -750,-275 -725,-275 ; -750,-250 -750,-337.5 -735,-337.5 ccw(c-735,-327.5) -725,-327.5 -725,-275 ; -162.5,200 -162.5,75 -125,75 ; 162.5,200 162.5,75 125,75 ; 750,-275 725,-275 725,-327.5 ccw(c735,-327.5) 735,-337.5 750,-337.5 750,-250 ; 793.75,-37.5 793.75,100 ; -725,-275 -675,-275 ; -675,-275 -625,-275 ; -675,-275 -675,-327.5 ccw(c-665,-327.5) -665,-337.5 -635,-337.5 ccw(c-635,-327.5) -625,-327.5 -625,-275 ; -625,-275 -575,-275 ; -575,-275 -575,-327.5 ccw(c-565,-327.5) -565,-337.5 -535,-337.5 ccw(c-535,-327.5) -525,-327.5 -525,-275 ; -575,-275 -525,-275 ; -525,-275 -475,-275 ; -475,-275 -425,-275 ; -475,-275 -475,-327.5 ccw(c-465,-327.5) -465,-337.5 -435,-337.5 ccw(c-435,-327.5) -425,-327.5 -425,-275 ; -425,-275 -375,-275 ; -375,-275 -375,-327.5 ccw(c-365,-327.5) -365,-337.5 -335,-337.5 ccw(c-335,-327.5) -325,-327.5 -325,-275 ; -375,-275 -325,-275 ; -325,-275 -275,-275 ; -275,-275 -225,-275 ; -275,-275 -275,-327.5 ccw(c-265,-327.5) -265,-337.5 -235,-337.5 ccw(c-235,-327.5) -225,-327.5 -225,-275 ; -225,-275 -175,-275 ; -175,-275 -175,-327.5 ccw(c-165,-327.5) -165,-337.5 -135,-337.5 ccw(c-135,-327.5) -125,-327.5 -125,-275 ; -175,-275 -125,-275 ; -125,-275 -75,-275 ; -125,75 -50,75 -50,-150 50,-150 50,75 125,75 ; -125,75 -125,100 cw(c-75,100) -75,150 75,150 cw(c75,100) 125,100 125,75 ; -75,-275 -25,-275 ; -75,-275 -75,-327.5 ccw(c-65,-327.5) -65,-337.5 -35,-337.5 ccw(c-35,-327.5) -25,-327.5 -25,-275 ; -25,-275 25,-275 ; 25,-275 25,-327.5 ccw(c35,-327.5) 35,-337.5 65,-337.5 ccw(c65,-327.5) 75,-327.5 75,-275 ; 25,-275 75,-275 ; 75,-275 125,-275 ; 125,-275 175,-275 ; 125,-275 125,-327.5 ccw(c135,-327.5) 135,-337.5 165,-337.5 ccw(c165,-327.5) 175,-327.5 175,-275 ; 175,-275 225,-275 ; 225,-275 225,-327.5 ccw(c235,-327.5) 235,-337.5 265,-337.5 ccw(c265,-327.5) 275,-327.5 275,-275 ; 225,-275 275,-275 ; 275,-275 325,-275 ; 325,-275 375,-275 ; 325,-275 325,-327.5 ccw(c335,-327.5) 335,-337.5 365,-337.5 ccw(c365,-327.5) 375,-327.5 375,-275 ; 375,-275 425,-275 ; 425,-275 475,-275 475,-327.5 cw(c465,-327.5) 465,-337.5 435,-337.5 cw(c435,-327.5) 425,-327.5 425,-275 ; 525,-327.5 525,-275 575,-275 575,-327.5 cw(c565,-327.5) 565,-337.5 535,-337.5 cw(c535,-327.5) 525,-327.5 ; 625,-327.5 625,-275 675,-275 675,-327.5 cw(c665,-327.5) 665,-337.5 635,-337.5 cw(c635,-327.5) 625,-327.5

## 15-91-16 [mil]
pads (18):
  round 134 hole 134: 1(-805,33) 1(805,33)
  rect 65x210 smd: 1(-750,-425) 2(-650,-425) 3(-550,-425) 4(-450,-425) 5(-350,-425) 6(-250,-425) 7(-150,-425) 8(-50,-425) 9(50,-425) 10(150,-425) 11(250,-425) 12(350,-425) 13(450,-425) 14(550,-425) 15(650,-425) 16(750,-425)
Top Overlay:
  region: 0,0 10,0 10,10 0,10
  lines w10: -843.75,-37.5 -843.75,-250 843.75,-250 843.75,-37.5 ; -843.75,100 -843.75,200 843.75,200 843.75,100
Mechanical 16:
  rectangle: -762.5,-425 -737.5,-275
  rectangle: -662.5,-425 -637.5,-275
  rectangle: -562.5,-425 -537.5,-275
  rectangle: -462.5,-425 -437.5,-275
  rectangle: -362.5,-425 -337.5,-275
  rectangle: -262.5,-425 -237.5,-275
  rectangle: -162.5,-425 -137.5,-275
  rectangle: -62.5,-425 -37.5,-275
  rectangle: 37.5,-425 62.5,-275
  rectangle: 137.5,-425 162.5,-275
  rectangle: 237.5,-425 262.5,-275
  rectangle: 337.5,-425 362.5,-275
  rectangle: 437.5,-425 462.5,-275
  rectangle: 737.5,-425 762.5,-275
  rectangle: 537.5,-425 562.5,-275
  rectangle: 637.5,-425 662.5,-275
  lines w8: 425,-275 475,-275 ; 525,-275 575,-275 ; 625,-275 675,-275 ; 725,-275 775,-275
  lines w10: -843.75,-37.5 -843.75,100 ; -800,-275 -775,-275 ; -800,-250 -800,-337.5 -785,-337.5 ccw(c-785,-327.5) -775,-327.5 -775,-275 ; -162.5,200 -162.5,75 -125,75 ; 162.5,200 162.5,75 125,75 ; 800,-275 775,-275 775,-327.5 ccw(c785,-327.5) 785,-337.5 800,-337.5 800,-250 ; 843.75,-37.5 843.75,100 ; -775,-275 -725,-275 ; -725,-275 -675,-275 ; -725,-275 -725,-327.5 ccw(c-715,-327.5) -715,-337.5 -685,-337.5 ccw(c-685,-327.5) -675,-327.5 -675,-275 ; -675,-275 -625,-275 ; -625,-275 -625,-327.5 ccw(c-615,-327.5) -615,-337.5 -585,-337.5 ccw(c-585,-327.5) -575,-327.5 -575,-275 ; -625,-275 -575,-275 ; -575,-275 -525,-275 ; -525,-275 -475,-275 ; -525,-275 -525,-327.5 ccw(c-515,-327.5) -515,-337.5 -485,-337.5 ccw(c-485,-327.5) -475,-327.5 -475,-275 ; -475,-275 -425,-275 ; -425,-275 -425,-327.5 ccw(c-415,-327.5) -415,-337.5 -385,-337.5 ccw(c-385,-327.5) -375,-327.5 -375,-275 ; -425,-275 -375,-275 ; -375,-275 -325,-275 ; -325,-275 -275,-275 ; -325,-275 -325,-327.5 ccw(c-315,-327.5) -315,-337.5 -285,-337.5 ccw(c-285,-327.5) -275,-327.5 -275,-275 ; -275,-275 -225,-275 ; -225,-275 -225,-327.5 ccw(c-215,-327.5) -215,-337.5 -185,-337.5 ccw(c-185,-327.5) -175,-327.5 -175,-275 ; -225,-275 -175,-275 ; -175,-275 -125,-275 ; -125,-275 -75,-275 ; -125,-275 -125,-327.5 ccw(c-115,-327.5) -115,-337.5 -85,-337.5 ccw(c-85,-327.5) -75,-327.5 -75,-275 ; -125,75 -50,75 -50,-150 50,-150 50,75 125,75 ; -125,75 -125,100 cw(c-75,100) -75,150 75,150 cw(c75,100) 125,100 125,75 ; -75,-275 -25,-275 ; -25,-275 -25,-327.5 ccw(c-15,-327.5) -15,-337.5 15,-337.5 ccw(c15,-327.5) 25,-327.5 25,-275 ; -25,-275 25,-275 ; 25,-275 75,-275 ; 75,-275 125,-275 ; 75,-275 75,-327.5 ccw(c85,-327.5) 85,-337.5 115,-337.5 ccw(c115,-327.5) 125,-327.5 125,-275 ; 125,-275 175,-275 ; 175,-275 175,-327.5 ccw(c185,-327.5) 185,-337.5 215,-337.5 ccw(c215,-327.5) 225,-327.5 225,-275 ; 175,-275 225,-275 ; 225,-275 275,-275 ; 275,-275 325,-275 ; 275,-275 275,-327.5 ccw(c285,-327.5) 285,-337.5 315,-337.5 ccw(c315,-327.5) 325,-327.5 325,-275 ; 325,-275 375,-275 ; 375,-275 425,-275 425,-327.5 cw(c415,-327.5) 415,-337.5 385,-337.5 cw(c385,-327.5) 375,-327.5 375,-275 ; 475,-327.5 475,-275 525,-275 525,-327.5 cw(c515,-327.5) 515,-337.5 485,-337.5 cw(c485,-327.5) 475,-327.5 ; 575,-327.5 575,-275 625,-275 625,-327.5 cw(c615,-327.5) 615,-337.5 585,-337.5 cw(c585,-327.5) 575,-327.5 ; 675,-327.5 675,-275 725,-275 725,-327.5 cw(c715,-327.5) 715,-337.5 685,-337.5 cw(c685,-327.5) 675,-327.5

## 22-23-2021 [mm]
pads (2):
  oval 1.5x3 hole 1: 1(-1.27,0) 2(1.27,0)
Top Overlay:
  lines w0.254: -2.54,1.27 -2.54,-3.175 2.54,-3.175 2.54,1.27 ; -2.54,1.27 -2.54,3.175 2.54,3.175 2.54,1.27 ; -2.54,1.27 2.54,1.27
